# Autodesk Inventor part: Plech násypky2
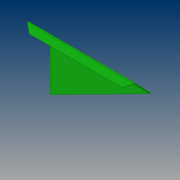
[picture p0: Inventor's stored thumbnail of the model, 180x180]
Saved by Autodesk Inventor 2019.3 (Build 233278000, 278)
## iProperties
Created: 2019-02
Part Number: Plech násypky2
Material: Ocel, legovaná
Document SubType Name: Plech
Designer: B-hon
Density: 7.73 g/cm^3
Sheet Metal Rule: Výchozí_mm
Appearance: Tmavě zelená
Author: B-hon
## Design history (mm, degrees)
node "Plocha1"
  sketch "Náčrt1"
    geometry: L1 (0, 0)-(380, 0); L2 (380, 0)-(380, 399.046); L3 (380, 399.046)-(0, 399.046); L4 (0, 399.046)-(0, 0)
    constraints: 8 end point, 2 parallel, 1 horizontal, 1 perpendicular
    dimensions: "d0" = 380 distance of L3.end L2.end
node "Obruba1"
sketch "Náčrt4"
  geometry: L1 (380, 113.384)-(380, 0) reference; L2 (380, 0)-(355.309, 116.163); L3 (0, 116.163)-(380, 116.163) reference; L4 (380, 114.773)-(380, 400.661) reference; L5 (380, 116.163)-(380, 0); 1 further point
  constraints: 4 end point, 1 collinear, 1 point on line
  dimensions: "d15" = 12 deg angle of L1 L2
extrude "Vysunutí2" cut sketch "Náčrt4" distance "d17" = 10; taper "d18" = 0 deg
sketch "Náčrt5"
  geometry: L1 (0, 397.43)-(-355.309, 397.43) reference; L2 (-355.309, 397.43)-(118.09, 157.573); L3 (118.09, 157.573)-(135.602, -112.632); L4 (135.602, -112.632)-(-574.447, -112.632); L5 (-355.309, 397.43)-(-380, 397.43) reference; L6 (-574.447, -112.632)-(-540.372, 435.331); L7 (-540.372, 435.331)-(-355.309, 397.43); 1 further point
  constraints: 10 end point, 1 parallel
  dimensions: "d19" = 26.87 deg angle of L2 L1
extrude "Vysunutí3" cut sketch "Náčrt5" distance "d20" = 10; taper "d21" = 0 deg
node "Upravit přímo1"
node "Upravit přímo2"
node "Obruba2"
node "Upravit přímo3"
sketch "Náčrt7"
  geometry: L1 (-36.745, 50.477)-(61.191, -47.459); L2 (61.191, -47.459)-(-76.237, -47.459); L3 (-76.237, -47.459)-(-36.745, 50.477); L4 (297.624, -31.782)-(398.933, -31.782); L5 (352.406, 0)-(0, 0) reference; L6 (398.933, -31.782)-(391.756, 62.349); L7 (352.406, 21)-(352.406, 0) reference; L8 (297.624, -31.782)-(391.756, 62.349); L9 (352.406, 0)-(352.406, 23); L10 (352.406, 0)-(0, 0) reference; L11 (0, 25)-(351.556, 25) reference; L12 (-9.268, 23)-(328.823, 23) reference; 2 further points
  constraints: 14 end point, 2 point on line, 1 horizontal, 1 parallel, 1 perpendicular
  dimensions: "d42" = 23 distance of L5.start L9.end; "d51" = 2 distance from line of L11 L12.start (derived); "d52" = 45 deg angle of L12 L1; "d53" = 45 deg angle of L7 L8
extrude "Vysunutí6" cut sketch "Náčrt7" distance "d54" = 6; taper "d55" = 0 deg
node "Těleso1"
feature "Deska1" dims "d1" = 2 (= Tloušťka)
sketch "Náčrt2"
  geometry: L1 through (-190, 0) direction (1, 0); L2 through (0, 57.5) direction (0, 1); L3 (0, 115)-(-380, 115); L4 (-380, 115)-(-380, 0)
  constraints: 6 end point, 1 horizontal, 1 perpendicular, 1 vertical
feature "Deska2" dims "d1" = 2 (= Tloušťka), "d2" = 2 (= ŠířkaVýštipu), "d3" = 1 (= HloubkaVýštipu), "d4" = 4 (= MinimálníZbytek), "d5" = 2 (= PřechodovýPoloměr), "d6" = 115, "d7" = 44 deg, "d8" = 2 (= PoloměrOhybu), "d9" = 8 (= VelikostRohovéhoVýštipu), "d10" = 2 (= VelikostMezery), "d11" = 2 (= VelikostJacobihoPoloměru), "MezeraVystřižení" = 0.01
feature "Ohyb1" dims "d1" = 2 (= Tloušťka), "d2" = 2 (= ŠířkaVýštipu), "d3" = 1 (= HloubkaVýštipu), "d4" = 4 (= MinimálníZbytek), "d5" = 2 (= PřechodovýPoloměr), "d6" = 115, "d7" = 44 deg, "d8" = 2 (= PoloměrOhybu), "MezeraVystřižení" = 0.01
feature "Roh1" dims "d6" = 115, "d7" = 44 deg, "d9" = 8 (= VelikostRohovéhoVýštipu), "d10" = 2 (= VelikostMezery), "d11" = 2 (= VelikostJacobihoPoloměru)
sketch "Náčrt6"
  geometry: L1 through (-176.203, 0) direction (1, 1.78e-16); L2 through (0, 12.5) direction (-1.51e-18, 1); L3 (0, 25)-(-352.406, 25); L4 (-352.406, 25)-(-352.406, 0)
  constraints: 6 end point, 1 horizontal, 1 perpendicular, 1 vertical
feature "Deska3" dims "d1" = 2 (= Tloušťka), "d28" = 2 (= ŠířkaVýštipu), "d29" = 1 (= HloubkaVýštipu), "d30" = 4 (= MinimálníZbytek), "d31" = 2 (= PřechodovýPoloměr), "d32" = 25, "d33" = 90 deg, "d34" = 2 (= PoloměrOhybu), "d35" = 8 (= VelikostRohovéhoVýštipu), "d36" = 2 (= VelikostMezery), "d37" = 2 (= VelikostJacobihoPoloměru), "MezeraVystřižení" = 0.01
feature "Ohyb2" dims "d1" = 2 (= Tloušťka), "d28" = 2 (= ŠířkaVýštipu), "d29" = 1 (= HloubkaVýštipu), "d30" = 4 (= MinimálníZbytek), "d31" = 2 (= PřechodovýPoloměr), "d32" = 25, "d33" = 90 deg, "d34" = 2 (= PoloměrOhybu), "MezeraVystřižení" = 0.01
feature "Roh2" dims "d32" = 25, "d33" = 90 deg, "d35" = 8 (= VelikostRohovéhoVýštipu), "d36" = 2 (= VelikostMezery), "d37" = 2 (= VelikostJacobihoPoloměru)
feature "Posunout1" dims "d24" = -2.43
feature "Posunout2" dims "d27" = -27.077
feature "Posunout3" dims "d47" = 9.268
other parameters: "Tloušťka" = 2 (derived), "KSoučinitel" = 4.4, "PoloměrOhybu" = 2 (= Tloušťka), "ŠířkaVýštipu" = 2 (= Tloušťka), "HloubkaVýštipu" = 1 (= 0.5 x Tloušťka), "VelikostRohovéhoVýštipu" = 8 (= 4 x Tloušťka), "MinimálníZbytek" = 4 (= 2 x Tloušťka), "PřechodovýPoloměr" = 2 (= PoloměrOhybu), "VelikostJacobihoPoloměru" = 2 (= PoloměrOhybu), "VelikostMezery" = 2 (= Tloušťka), "d22" = 0, "d23" = 0, "d25" = 0, "d26" = 0, "d45" = 0, "d46" = 0
